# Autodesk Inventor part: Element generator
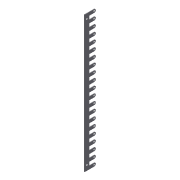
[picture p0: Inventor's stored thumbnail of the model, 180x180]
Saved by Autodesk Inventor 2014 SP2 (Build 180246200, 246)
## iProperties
Created: 2015-04
Part Number: Element generator
Material: Generic
Document SubType Name: Modeling
Designer: SFC
Density: 1 g/cm^3
Appearance: Default
Author: SFC
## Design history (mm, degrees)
sketch "Sketch1"
  geometry: L1 (0, 0)-(0, 512); L2 (0, 0)-(36, 0); L3 (36, 12)-(18, 12); L4 (18, 12)-(18, 25); L5 (18, 25)-(36, 25); L6 (36, 37)-(18, 37); L7 (18, 37)-(18, 50); L8 (18, 50)-(36, 50); L9 (36, 62)-(18, 62); L10 (18, 62)-(18, 75); L11 (18, 75)-(36, 75); L12 (36, 87)-(18, 87); L13 (18, 87)-(18, 100); L14 (18, 100)-(36, 100); L15 (36, 112)-(18, 112); L16 (18, 112)-(18, 125); L17 (18, 125)-(36, 125); L18 (36, 137)-(18, 137); L19 (18, 137)-(18, 150); L20 (18, 150)-(36, 150); L21 (36, 162)-(18, 162); L22 (18, 162)-(18, 175); L23 (18, 175)-(36, 175); L24 (36, 187)-(18, 187); L25 (18, 187)-(18, 200); L26 (18, 200)-(36, 200); L27 (36, 212)-(18, 212); L28 (18, 212)-(18, 225); L29 (18, 225)-(36, 225); L30 (36, 237)-(18, 237); L31 (18, 237)-(18, 250); L32 (18, 250)-(36, 250); L33 (36, 262)-(18, 262); L34 (18, 262)-(18, 275); L35 (18, 275)-(36, 275); L36 (36, 287)-(18, 287); L37 (18, 287)-(18, 300); L38 (18, 300)-(36, 300); L39 (36, 312)-(18, 312); L40 (18, 312)-(18, 325); L41 (18, 325)-(36, 325); L42 (36, 337)-(18, 337); L43 (18, 337)-(18, 350); L44 (18, 350)-(36, 350); L45 (36, 362)-(18, 362); L46 (18, 362)-(18, 375); L47 (18, 375)-(36, 375); L48 (36, 387)-(18, 387); L49 (18, 387)-(18, 400); L50 (18, 400)-(36, 400); L51 (36, 412)-(18, 412); L52 (18, 412)-(18, 425); L53 (18, 425)-(36, 425); L54 (36, 437)-(18, 437); L55 (18, 437)-(18, 450); L56 (18, 450)-(36, 450); L57 (36, 462)-(18, 462); L58 (18, 462)-(18, 475); L59 (18, 475)-(36, 475); L60 (36, 487)-(18, 487); L61 (18, 487)-(18, 500); L62 (18, 500)-(36, 500); L63 (36, 512)-(0, 512); C1 r 3 at (36, 6); C2 r 3 at (36, 31); C3 r 3 at (36, 56); C4 r 3 at (36, 81); C5 r 3 at (36, 106); C6 r 3 at (36, 131); C7 r 3 at (36, 156); C8 r 3 at (36, 181); C9 r 3 at (36, 206); C10 r 3 at (36, 231); C11 r 3 at (36, 256); C12 r 3 at (36, 281); C13 r 3 at (36, 306); C14 r 3 at (36, 331); C15 r 3 at (36, 356); C16 r 3 at (36, 381); C17 r 3 at (36, 406); C18 r 3 at (36, 431); C19 r 3 at (36, 456); C20 r 3 at (36, 481); C21 r 3 at (36, 506); A1 r 6 centre (36, 6) between (36, 0) and (36, 12); A2 r 6 centre (36, 31) between (36, 25) and (36, 37); A3 r 6 centre (36, 56) between (36, 50) and (36, 62); A4 r 6 centre (36, 81) between (36, 75) and (36, 87); A5 r 6 centre (36, 106) between (36, 100) and (36, 112); A6 r 6 centre (36, 131) between (36, 125) and (36, 137); A7 r 6 centre (36, 156) between (36, 150) and (36, 162); A8 r 6 centre (36, 181) between (36, 175) and (36, 187); A9 r 6 centre (36, 206) between (36, 200) and (36, 212); A10 r 6 centre (36, 231) between (36, 225) and (36, 237); A11 r 6 centre (36, 256) between (36, 250) and (36, 262); A12 r 6 centre (36, 281) between (36, 275) and (36, 287); A13 r 6 centre (36, 306) between (36, 300) and (36, 312); A14 r 6 centre (36, 331) between (36, 325) and (36, 337); A15 r 6 centre (36, 356) between (36, 350) and (36, 362); A16 r 6 centre (36, 381) between (36, 375) and (36, 387); A17 r 6 centre (36, 406) between (36, 400) and (36, 412); A18 r 6 centre (36, 431) between (36, 425) and (36, 437); A19 r 6 centre (36, 456) between (36, 450) and (36, 462); A20 r 6 centre (36, 481) between (36, 475) and (36, 487); A21 r 6 centre (36, 506) between (36, 500) and (36, 512)
  constraints: 126 end point, 42 centre point, 42 point on circle, 21 coincident, 4 tangent, 3 parallel, 2 equal radius, 2 perpendicular, 1 vertical, 1 vertical alignment
  dimensions: "d1" = 36 distance of L1.start L2.end; "d2" = 6 radius of A1; "d3" = 25 distance between parallel lines of L5 L2; "d4" = 18 distance between parallel lines of L1 L4; "d6" = 6 diameter of C1
extrude "Extrusion1" new body sketch "Sketch1" distance "d14" = 2; taper "d15" = 0 deg
sketch "Sketch2"
  geometry: L1 (-512, 0)-(0, 0) reference; L2 (-12, 18)-(-25, 18) reference; L3 (-487, 18)-(-500, 18) reference; 4 further points
  constraints: 2 midpoint, 2 vertical alignment, 1 horizontal alignment
  dimensions: "d16" = 9 distance from line of L1 point (-493.5, 9)
hole "Hole1" sketch "Sketch2" at (-493.5, 9), (-18.5, 9) diameter "d17" = 6; stored, may be unused: countersink angle "d21" = 90 deg, drill point angle "d23" = 118 deg; dims "d18" = 6, "d19" = 4, "d20" = 2, "d22" = 8
body "Solid1"
